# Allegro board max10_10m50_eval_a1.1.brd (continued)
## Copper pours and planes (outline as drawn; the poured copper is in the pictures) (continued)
1.8V_AVDD on BOTTOM (solid shape): 71.63,61.09 72.77,61.09 73.15,60.71 73.15,59.31 73.03,59.18 73.03,55.63 71.5,55.63 70.1,55.75 70.1,56.01 70.87,56.01 70.87,56.39 70.48,56.39 70.48,56.01 70.1,56.01 70.1,57.53 72.39,57.53 72.39,58.04 71.88,58.04 71.88,57.53 70.1,57.53 70.61,58.04 70.61,58.93 70.74,59.05 71.25,59.05 71.37,58.93 72.26,58.93 72.26,59.56 72.9,59.56 72.9,59.94 72.52,59.94 72.52,59.56 72.26,59.56 72.26,60.2 72.9,60.2 72.9,60.58 72.52,60.58 72.52,60.2 72.26,60.2 72.26,60.45 72.14,60.58 70.99,60.58 70.61,60.96 70.61,61.34 70.74,61.47 71.25,61.47
1.8V_DVDD on TOP (solid shape): 68.07,57.66 68.07,57.28 67.94,57.15 62.87,57.15 62.48,56.77 62.48,55.12 62.36,54.99 61.98,54.99 61.72,55.24 61.72,57.15 62.48,57.91 67.82,57.91
1.8V_DVDD on BOTTOM (solid shape): 63.37,57.4 64.9,57.4 64.9,54.61 62.36,54.61 61.98,54.99 61.98,56.26 64.01,56.26 64.01,56.77 63.5,56.77 63.5,56.26 61.98,56.26 61.98,57.4 62.23,57.66 63.12,57.66
1.8V_DVDD on ART04 (solid shape): 71.25,65.91 71.25,65.15 70.99,64.9 70.74,64.9 69.22,66.42 64.77,66.42 63.88,65.53 63.88,57.91 63.5,57.53 63.5,55.88 62.48,54.86 61.98,54.86 61.72,55.12 61.72,57.28 62.99,58.55 62.99,62.1 62.1,62.99 62.1,65.91 63.5,67.31 69.85,67.31
1.8V_MIPITX on BOTTOM (solid shape): 32.77,32.38 34.42,32.38 34.42,31.88 32.51,31.88 32,32.38 29.84,32.38 29.59,32.13 26.42,32.13 26.42,32.51 27.18,32.51 27.56,32.89 32.26,32.89
1.8V_OV10640 on BOTTOM (solid shape): 78.74,32.51 84.71,32.51 84.96,32.26 84.96,30.99 81.92,30.99 81.28,31.62 84.07,31.62 84.07,32.13 82.93,32.13 82.93,31.62 82.17,31.62 82.17,32.13 81.66,32.13 81.66,31.62 81.28,31.62 81.03,31.88 78.61,31.88 78.11,32.38 76.71,32.38 76.71,32.89 78.36,32.89
1.8V_PVDD on BOTTOM (solid shape): 69.6,57.53 69.6,55.75 66.8,55.75 66.8,54.48 65.79,54.48 65.79,56.01 69.22,56.01 69.22,56.39 68.45,56.39 68.45,56.01 68.2,56.01 68.2,56.39 67.82,56.39 67.82,56.01 65.79,56.01 65.79,57.4 66.8,57.4 66.8,56.77 67.94,56.77 68.33,57.15 68.33,57.53 68.58,57.78 69.34,57.78
2.5V on BOTTOM (solid shape): 40.26,49.15 39.75,48.64 38.73,48.64 38.48,48.89 38.48,50.16 38.73,50.42 41.15,50.42
2.5V on BOTTOM (solid shape): 27.23,55.78 27.38,55.63 27.94,55.63 28.32,55.24 28.32,54.61 25.4,54.61 25.02,54.99 25.02,55.5 26.29,55.5 26.29,56.01 25.78,56.01 25.78,55.5 25.02,55.5 25.02,56.39 25.27,56.64 27.23,56.64
2.5V on TOP: 25.91,56.64 27.23,56.64 27.23,55.78 27.38,55.63 28.32,55.63 28.7,56.01 30.1,56.01 30.23,55.88 30.23,54.48 29.97,54.23 25.4,54.23 25.02,54.61 25.02,56.01 25.15,56.13 25.65,56.13 25.78,56.26 25.78,56.52 ; 1 cut-out
2.5V on VCC03: 1.78,22.23 12.45,22.23 13.21,22.99 13.21,37.97 13.97,38.73 15.88,38.73 22.99,45.85 24.26,45.85 26.04,47.62 26.04,51.69 24.13,53.59 24.13,56.13 24.64,56.64 33.53,56.64 41.91,48.26 41.91,42.04 41.66,41.78 28.07,41.78 21.59,35.31 21.59,29.84 22.23,29.21 24.51,29.21 25.02,28.7 25.02,14.35 26.29,13.08 31.11,13.08 31.88,13.84 41.4,13.84 47.5,19.94 47.5,20.95 53.21,26.67 53.21,32.77 54.48,34.04 60.07,34.04 61.72,32.38 82.55,32.38 87.25,27.69 91.44,27.69 92.33,26.8 92.33,6.86 92.2,6.73 1.65,6.73 1.65,22.1
2.5V_CORE on BOTTOM (solid shape): 43.43,50.04 43.43,47.12 43.18,46.86 41.91,46.86 41.91,50.42 43.05,50.42
2.5V_VCCA on BOTTOM (solid shape): 53.47,40.89 53.47,40.39 52.96,40.39 52.83,40.51 52.83,40.89 52.58,41.15 51.31,41.15 51.18,41.27 51.18,41.4 51.31,41.53 52.83,41.53
2.5V_VCCA on BOTTOM (solid shape): 41.15,44.45 41.4,44.2 42.8,44.2 43.18,43.81 43.81,43.81 43.81,42.93 45.47,41.27 46.99,41.27 47.24,41.02 47.24,40.89 46.23,40.89 45.97,40.64 44.7,40.64 42.29,43.05 43.56,43.05 43.56,43.43 43.18,43.43 43.18,43.05 42.29,43.05 42.16,43.18 40.39,43.18 39.62,43.94 39.62,44.45 40.39,44.45 40.39,44.96 39.88,44.96 39.88,44.45 39.62,44.45 39.62,45.72 40.39,45.72 40.39,46.23 39.88,46.23 39.88,45.72 39.62,45.72 39.62,47.75 39.88,48.01 41.15,48.01
3.3V on TOP (solid shape): 15.24,57.53 15.24,56.26 14.1,56.26 13.84,56.52 14.99,56.52 14.99,56.9 14.61,56.9 14.61,56.52 13.84,56.52 13.84,57.53 14.1,57.78 14.99,57.78
3.3V on TOP (solid shape): 19.81,12.7 43.18,12.7 43.94,11.94 43.94,7.37 44.2,7.11 50.93,7.11 51.44,7.62 54.48,7.62 54.86,7.24 54.86,6.6 54.36,6.1 43.56,6.1 42.67,6.99 42.67,11.3 42.55,11.43 17.65,11.43 17.02,12.07 17.02,13.21 17.27,13.46 19.05,13.46
3.3V on BOTTOM (solid shape): 73.03,68.33 73.03,66.42 71.75,66.42 71.75,68.33 71.88,68.45 72.9,68.45
3.3V on BOTTOM (solid shape): 54.86,7.24 54.86,6.6 54.36,6.1 51.44,6.1 51.18,6.35 51.18,6.86 51.44,7.11 51.94,7.11 52.32,7.49 54.61,7.49
3.3V on BOTTOM (solid shape): 87,36.83 87,35.69 86.11,34.8 84.07,34.8 84.07,35.43 85.34,35.43 85.34,35.94 84.84,35.94 84.84,35.43 84.07,35.43 84.07,36.83 84.33,37.08 86.74,37.08
3.3V on BOTTOM (solid shape): 64.14,13.32 64.14,12.32 63.88,12.07 60.45,12.07 60.33,12.19 60.33,12.57 60.96,12.57 60.96,12.95 60.58,12.95 60.58,12.57 60.33,12.57 60.33,13.34 60.96,13.34 61.09,13.47 63.99,13.47
3.3V on BOTTOM (solid shape): 51.74,39.49 51.74,38.81 51.81,38.73 51.81,38.1 51.43,37.72 49.91,37.72 49.78,37.85 49.78,38.1 49.91,38.23 49.91,38.27 50.01,38.37 50.01,38.67 49.91,38.77 49.91,39.24 50.16,39.24 50.29,39.12 50.67,39.12 51.22,39.67 51.56,39.67
3.3V on BOTTOM (solid shape): 37.21,74.8 37.21,73.28 36.96,73.02 35.56,73.02 35.43,72.9 35.43,72.01 32.26,72.01 32,71.75 30.35,71.75 30.23,71.88 30.23,72.64 34.54,72.64 34.54,73.15 33.4,73.15 33.4,72.64 32.64,72.64 32.64,73.15 32.13,73.15 32.13,72.64 30.23,72.64 30.23,73.28 29.97,73.53 29.46,73.53 29.46,74.8 29.72,75.06 36.96,75.06
3.3V on ART04 (solid shape): 12.95,25.91 12.95,20.07 19.3,13.72 19.3,12.07 19.05,11.81 16.76,11.81 10.41,18.16 10.41,25.91 10.79,26.29 12.57,26.29
3.3V on ART04 (solid shape): 63.76,13.21 63.75,13.21 63.75,12.07 63.63,11.94 59.05,11.94 59,11.89 58.99,11.88 58.75,11.73 58.6,11.49 58.6,11.48 56.77,9.65 56.77,8.13 55.24,6.6 51.44,6.6 51.18,6.86 51.18,8.25 51.82,8.89 54.61,8.89 55.12,9.4 55.12,10.16 56.79,11.83 56.8,11.83 57.09,12 57.26,12.29 57.26,12.3 58.42,13.46 63.51,13.46
3.3V on BOTTOM: 26.92,34.54 26.92,35.05 27.05,35.18 27.56,35.18 27.69,35.31 27.69,37.34 27.43,37.59 26.16,37.59 24.77,36.2 24.77,25.65 23.11,24 20.83,24 19.05,25.78 17.78,25.78 17.27,26.29 10.79,26.29 10.16,25.65 10.16,24.13 10.79,23.49 14.61,23.49 15.49,22.61 23.88,22.61 26.04,24.77 26.04,34.42 26.16,34.54 ; 1 cut-out
3.3V on VCC03: 51.82,39.75 51.82,39.5 51.56,39.24 50.29,39.24 47.75,41.78 42.67,41.78 42.42,42.04 42.42,48.51 33.78,57.15 24.38,57.15 23.62,56.39 23.62,53.47 25.53,51.56 25.53,47.75 24.13,46.35 22.86,46.35 15.75,39.24 13.84,39.24 12.7,38.1 12.7,23.11 12.32,22.73 1.78,22.73 1.65,22.86 1.65,29.59 1.78,29.72 7.24,29.72 8.51,30.99 8.51,33.53 8,34.04 7.11,34.04 5.59,35.56 5.59,37.34 6.73,38.48 8,38.48 8.64,39.12 8.64,41.15 6.86,42.93 1.91,42.93 1.65,43.18 1.65,74.55 75.18,74.55 75.44,74.3 75.44,67.82 74.8,67.18 49.66,67.18 48.9,66.42 48.9,60.2 50.04,59.05 60.33,59.05 62.74,56.64 92.33,56.64 92.33,35.05 92.2,34.92 85.72,34.92 85.34,35.31 85.34,36.83 85.6,37.08 88.65,37.08 89.15,37.59 89.15,51.56 88.77,51.94 72.39,51.94 65.91,45.47 63.02,45.47 58.07,40.51 52.58,40.51
3.3V on ART04: 29.34,36.7 27.81,35.18 26.42,35.18 25.4,36.2 25.4,38.61 24,40 24,40.13 28.45,40.13 29.21,39.37 32,39.37 32.77,40.13 32.77,40.51 32.51,40.77 29.72,40.77 28.57,41.91 28.57,45.09 29.84,46.35 34.16,46.35 34.29,46.23 34.29,45.97 32.51,44.2 32.51,42.8 34.67,40.64 34.67,36.96 34.42,36.7
3.3V_DVDD on BOTTOM (solid shape): 73.03,65.02 73.79,64.26 73.79,62.48 73.15,62.48 72.39,63.25 71.5,63.25 71.5,63.37 73.15,63.37 73.15,63.88 72.64,63.88 72.64,63.37 71.5,63.37 71.37,63.5 72.26,63.5 72.26,63.88 71.88,63.88 71.88,63.5 71.37,63.5 71.25,63.63 69.72,63.63 69.72,63.88 70.48,63.88 70.48,64.01 73.28,64.01 73.28,64.52 72.77,64.52 72.77,64.01 72.01,64.01 72.01,64.52 71.5,64.52 71.5,64.01 70.48,64.01 70.48,64.26 70.1,64.26 70.1,63.88 69.72,63.88 69.72,64.64 71.25,64.64 71.75,65.15 71.75,65.66 73.03,65.66
3.3V_MIPITX on BOTTOM (solid shape): 29.84,34.29 34.42,34.29 34.42,32.89 32.89,32.89 32.38,33.4 27.3,33.4 27.05,33.66 26.42,33.66 26.42,34.04 27.05,34.04 27.56,34.54 29.59,34.54
3.3V_OV5640 on TOP (solid shape): 57.28,13.34 57.28,11.43 56.77,10.92 55.12,10.92 55.12,13.34 55.5,13.72 56.9,13.72
3.3V_OV5640 on BOTTOM (solid shape): 59.18,13.34 59.82,13.34 59.82,12.83 59.18,12.83 58.93,12.57 57.28,12.57 56.77,12.07 55.63,12.07 55.37,12.32 55.37,13.34 55.63,13.59 58.93,13.59
3.3V_OV10640 on BOTTOM (solid shape): 81.66,33.91 84.96,33.91 84.96,32.89 79.38,32.89 78.87,33.4 76.71,33.4 76.71,34.16 76.96,34.42 81.15,34.42
3.3V_SI5338 on TOP (solid shape): 23.11,57.15 23.11,53.59 21.34,51.82 19.05,51.82 18.67,52.2 18.67,53.47 19.05,53.47 19.05,52.96 19.3,52.7 20.32,52.7 20.45,52.83 21.21,52.83 21.21,53.21 20.83,53.21 20.83,52.83 20.45,52.83 20.57,52.96 20.57,53.59 21.08,53.59 21.21,53.72 22.1,53.72 22.1,54.1 21.72,54.1 21.72,53.72 21.21,53.72 21.34,53.85 21.34,54.36 21.97,54.36 22.23,54.61 22.23,56.52 21.97,56.77 18.03,56.77 17.91,56.64 17.91,56.39 17.78,56.26 17.02,56.26 16.89,56.13 15.75,56.13 15.75,56.52 17.53,56.52 17.53,56.9 17.14,56.9 17.14,56.52 16.38,56.52 16.38,56.9 16,56.9 16,56.52 15.75,56.52 15.75,57.02 22.1,57.02 22.1,57.4 21.72,57.4 21.72,57.02 21.46,57.02 21.46,57.4 21.08,57.4 21.08,57.02 15.75,57.02 16,57.28 17.4,57.28 17.91,57.78 22.48,57.78
5V on TOP (solid shape): 92.08,60.96 92.08,59.31 91.82,59.05 90.04,59.05 89.53,58.55 89.53,56.9 90.04,56.39 92.2,56.39 92.96,55.63 92.96,51.82 92.71,51.56 91.31,51.56 91.31,52.45 92.46,52.45 92.46,52.96 91.95,52.96 91.95,52.45 91.31,52.45 91.31,54.86 90.93,55.24 89.03,55.24 87.63,56.64 87.63,59.69 89.15,61.21 91.82,61.21
5V on BOTTOM (solid shape): 24.13,30.48 24.38,30.23 24.38,28.19 24.13,27.94 22.99,27.94 22.73,28.19 22.73,30.23 23.11,30.61 23.11,31.88 24.13,31.88
5V on BOTTOM (solid shape): 29.46,61.34 29.46,58.55 28.45,58.55 28.45,58.67 27.94,59.18 26.04,59.18 25.78,59.44 28.7,59.44 28.7,59.94 28.19,59.94 28.19,59.44 25.78,59.44 25.4,59.82 25.4,61.21 25.78,61.59 29.21,61.59
5V on BOTTOM (solid shape): 51.31,62.23 51.82,62.23 52.58,61.47 52.58,60.71 52.2,60.32 50.16,60.32 48.77,61.72 48.77,62.48 50.16,62.48 50.16,62.99 49.66,62.99 49.66,62.48 48.77,62.48 48.77,63.63 49.91,63.63
5V on BOTTOM (solid shape): 22.86,74.3 22.86,72.14 22.61,71.88 20.32,71.88 19.81,72.39 19.81,72.64 22.48,72.64 22.48,73.15 21.97,73.15 21.97,72.64 21.21,72.64 21.21,73.15 20.7,73.15 20.7,72.64 19.81,72.64 19.81,74.3 20.07,74.55 22.61,74.55
5V on TOP: 18.03,39.88 18.03,35.31 17.78,35.05 16.51,35.05 16.26,35.31 16.26,37.85 16.89,38.48 16.89,39.88
5V on BOTTOM: 11.43,38.99 16.64,38.99 18.41,37.21 18.41,35.56 18.16,35.31 16.13,35.31 15.75,35.69 15.75,36.7 14.99,37.46 13.46,37.46 13.08,37.85 11.43,37.85
5V on VCC03: 60.45,59.56 62.87,57.15 92.2,57.15 92.33,57.28 92.33,74.55 76.2,74.55 75.95,74.3 75.95,67.44 75.18,66.67 50.04,66.67 49.4,66.04 49.4,60.45 50.29,59.56
5V on ART04: 22.23,27.94 16.76,33.4 14.86,33.4 10.29,37.97 10.29,41.78 4.45,47.62 4.45,66.67 9.14,71.37 15.62,71.37 18.8,74.55 22.1,74.55 22.35,74.3 22.35,73.15 23.37,72.14 25.91,72.14 27.94,74.17 32.13,74.17 33.78,72.52 41.53,72.52 42.93,71.12 48.26,71.12 52.7,66.67 52.7,60.71 52.32,60.32 49.91,60.32 45.47,64.77 33.02,64.77 28.45,60.2 24.89,60.2 20.32,64.77 8.89,64.77 7.75,65.91 7.37,65.91 6.99,65.53 6.99,61.59 7.62,60.96 7.62,47.37 16.38,38.61 19.68,38.61 21.84,36.45 21.84,35.31 24.77,32.38 24.77,28.19 24.51,27.94 ; 1 cut-out
5V_DCIN on TOP (solid shape): outline of 86 points within 5.71,12.07 14.1,19.05
5V_MONITOR on BOTTOM (solid shape): 25.02,21.97 25.02,19.05 21.59,19.05 21.34,18.8 20.19,18.8 19.81,18.41 18.92,18.41 18.92,18.92 19.56,18.92 19.68,19.05 21.08,19.05 21.08,19.43 20.7,19.43 20.7,19.05 20.45,19.05 20.45,19.43 20.07,19.43 20.07,19.05 19.68,19.05 19.68,19.43 20.07,19.81 20.07,22.23 24.77,22.23
5V_MONITOR on TOP: 25.78,19.81 25.53,20.07 19.94,20.07 19.43,20.57 15.88,20.57 15.62,20.83 15.62,22.73 18.8,22.73 19.05,22.48 21.84,22.48 22.48,23.11 22.48,26.42 24.13,28.07 24.13,34.29 23.62,34.8 18.8,34.8 18.41,35.18 18.41,37.72 18.8,38.1 18.8,39.88 20.7,39.88 23.5,37.08 25.91,37.08 26.29,36.7 26.29,35.18 27.69,33.78 27.69,26.42 26.04,24.77 26.04,20.19 26.1,20.13
5V_R1.2CORE on TOP (solid shape): 15.49,28.19 15.49,25.91 15.24,25.65 14.73,25.65 14.48,25.91 14.48,28.07 14.73,28.32 15.37,28.32
5V_R1.2CORE on TOP (solid shape): 21.84,28.19 21.59,27.94 20.32,27.94 20.19,28.07 18.92,28.07 18.8,28.19 18.8,28.96 18.92,29.08 19.56,29.08 19.94,29.46 19.94,30.61 20.19,30.86 21.84,30.86
5V_R1.2CORE on BOTTOM (solid shape): 22.35,28.19 22.1,27.94 19.94,27.94 19.68,28.19 19.68,30.48 21.59,30.48 21.59,30.99 21.08,30.99 21.08,30.48 19.68,30.48 19.68,30.86 20.7,31.88 22.35,31.88
5V_R1.2VCCIO on TOP (solid shape): 90.93,54.61 90.93,53.47 90.3,52.83 90.3,51.56 89.15,51.56 88.27,52.45 89.66,52.45 89.66,52.96 89.15,52.96 89.15,52.45 88.27,52.45 88.27,54.23 88.9,54.23 88.9,54.61 88.52,54.61 88.52,54.23 88.27,54.23 88.27,54.86 90.68,54.86
5V_R1.2VCCIO on BOTTOM (solid shape): 90.93,54.48 90.93,52.2 89.53,52.2 89.03,52.7 88.39,52.7 88.27,52.83 90.04,52.83 90.04,53.34 89.53,53.34 89.53,52.83 88.27,52.83 88.27,54.36 88.52,54.61 90.81,54.61
5V_R1.8 on BOTTOM (solid shape): 52.58,64.64 53.09,64.64 53.09,63.25 53.47,62.86 53.59,62.86 53.72,62.74 53.72,61.98 53.59,61.85 52.83,61.85 52.07,62.61 51.69,62.61 49.91,64.39 52.07,64.39 52.07,64.9 51.56,64.9 51.56,64.39 49.91,64.39 49.78,64.52 48.77,64.52 48.77,65.53 51.69,65.53
5V_R2.5 on TOP (solid shape): 31.75,60.71 33.4,60.71 33.53,60.58 33.53,59.18 33.27,58.93 32.26,58.93 31.5,58.17 30.48,58.17 30.48,59.05 30.35,59.18 30.35,59.56 31.5,59.56 31.5,60.07 30.99,60.07 30.99,59.56 30.35,59.56 30.35,60.96 31.5,60.96
5V_R2.5 on BOTTOM (solid shape): 33.91,60.45 33.91,57.91 33.53,57.91 33.53,58.42 33.27,58.67 32.38,58.67 32.26,58.55 30.35,58.55 30.35,59.44 31.5,59.44 31.5,59.94 30.99,59.94 30.99,59.44 30.35,59.44 30.35,60.45 30.61,60.71 33.66,60.71
5V_R3.3 on BOTTOM (solid shape): 31.62,69.34 31.62,67.69 31.37,67.44 30.48,67.44 30.23,67.69 30.23,69.85 30.35,69.98 30.99,69.98
5V_R3.3 on BOTTOM (solid shape): 26.16,70.74 26.8,70.74 26.92,70.61 26.92,69.85 26.8,69.72 25.65,69.72 24.51,68.58 21.46,68.58 21.08,68.96 21.08,69.85 22.48,69.85 22.48,70.36 21.97,70.36 21.97,69.85 21.08,69.85 21.08,71.12 25.78,71.12
GND on TOP (solid shape): 69.22,59.05 64.14,59.05 64.14,64.14 69.22,64.14
GND on TOP (solid shape): 21.84,34.04 21.84,31.62 19.94,31.62 18.54,33.02 17.91,33.02 17.65,32.77 17.65,26.92 16,26.92 16,29.21 16.89,29.21 16.89,31.5 16.64,31.75 16.64,34.04 16.89,34.29 21.59,34.29
GND on TOP (solid shape): 15.49,29.59 15.49,28.83 15.37,28.7 14.48,28.7 14.1,28.32 14.1,26.92 13.84,26.67 10.54,26.67 10.16,27.05 10.16,29.46 13.72,29.46 13.97,29.72 15.37,29.72
GND on TOP (solid shape): 57.15,69.22 57.15,68.2 54.61,65.66 50.8,65.66 50.55,65.91 54.23,65.91 54.23,66.29 53.85,66.29 53.85,65.91 53.59,65.91 53.59,66.29 53.21,66.29 53.21,65.91 50.55,65.91 50.55,70.99 55.37,70.99
GND on BOTTOM (solid shape): 20.83,54.1 18.54,54.1 18.54,56.39 20.83,56.39
GND on BOTTOM (solid shape): 21.84,42.29 16.26,42.29 16.26,47.88 21.84,47.88
GND on BOTTOM (solid shape): 17.78,31.37 17.78,26.92 17.53,26.67 16.08,26.67 15.88,26.87 15.88,31.37 16.13,31.62 17.53,31.62
GND on BOTTOM (solid shape): 35.43,40.13 36.7,40.13 36.7,39.12 35.43,39.12 35.18,38.86 34.92,38.86 34.8,38.99 34.8,40.13 34.92,40.26 35.31,40.26
GND on BOTTOM (solid shape): 29.97,31.12 29.97,30.1 29.72,29.84 28.19,29.84 28.07,29.97 28.07,31.12 29.21,31.12 29.46,31.37 29.72,31.37
GND on BOTTOM (solid shape): 64.14,66.55 60.33,66.55 59.31,65.53 58.55,65.53 58.29,65.79 58.29,66.55 59.44,67.69 64.14,67.69
GND on BOTTOM (solid shape): 19.3,20.7 19.68,20.32 19.68,20.07 19.3,19.69 18.92,19.69 18.54,19.3 17.14,19.3 16.76,18.92 16.76,18.41 16.64,18.29 16.13,18.29 15.88,18.54 15.88,21.97 16.13,22.23 19.3,22.23
GND on BOTTOM (solid shape): 24.89,61.34 24.89,59.56 25.91,58.55 27.81,58.55 28.07,58.29 28.07,57.91 27.81,57.66 26.04,57.66 25.78,57.4 22.23,57.4 21.21,58.42 21.21,61.21 21.59,61.59 24.64,61.59
GND on BOTTOM (solid shape): 44.83,45.97 44.83,43.56 44.7,43.43 44.32,43.43 43.94,44.58 43.43,44.58 43.18,44.83 41.91,44.83 41.91,45.85 42.85,45.85 43.23,46.23 44.58,46.23
GND on BOTTOM (solid shape): 83.06,25.65 82.8,25.4 82.17,25.4 81.66,24.89 81.41,24.89 81.28,25.02 81.28,28.83 82.17,28.83 82.17,29.34 81.66,29.34 81.66,28.83 81.28,28.83 81.28,29.84 81.41,29.97 83.06,29.97
GND on BOTTOM (solid shape): 29.08,74.8 29.08,73.41 28.83,73.15 28.83,70.87 29.72,70.87 29.72,68.71 28.07,68.71 28.07,74.42 27.94,74.55 26.8,74.55 25.78,73.53 25.78,72.14 25.53,71.88 23.5,71.88 23.5,74.8 23.75,75.06 28.83,75.06
GND on BOTTOM (solid shape): 15.49,29.46 15.49,26.92 15.24,26.67 10.54,26.67 10.16,27.05 10.16,28.96 15.24,28.96 15.24,29.34 14.86,29.34 14.86,28.96 10.16,28.96 10.16,29.46 13.97,29.46 14.1,29.59 15.37,29.59
GND on BOTTOM (solid shape): 32.26,70.99 35.43,70.99 35.43,69.6 35.18,69.34 32.26,69.34 31.75,69.85 34.54,69.85 34.54,70.36 33.4,70.36 33.4,69.85 32.64,69.85 32.64,70.36 32.13,70.36 32.13,69.85 31.75,69.85 31.24,70.36 30.35,70.36 30.23,70.48 30.23,71.25 30.35,71.37 31.88,71.37
GND on BOTTOM (solid shape): 70.61,52.83 69.22,51.43 67.56,51.43 67.31,51.69 67.31,54.61 70.23,54.61 70.23,54.99 69.47,54.99 69.47,54.61 69.22,54.61 69.22,54.99 68.45,54.99 68.45,54.61 68.2,54.61 68.2,54.99 67.82,54.99 67.82,54.61 67.31,54.61 67.31,54.99 67.56,55.24 70.61,55.24
GND on BOTTOM (solid shape): 12.83,44.45 13.59,44.45 13.59,44.07 12.75,44.07 12.75,44.07 11.26,44.07 11.26,43.89 11.18,43.81 11.18,42.93 10.29,42.93 10.16,42.8 10.16,42.62 10.11,42.62 10.11,41.02 11.6,41.02 12.83,41.02 13.21,41.02 13.21,41.4 12.83,41.4 12.83,41.02 11.6,41.02 11.6,41.2 11.68,41.27 11.68,42.16 12.32,42.16 12.32,41.66 13.59,41.66 13.59,40.64 13.46,40.51 10.29,40.51 9.78,41.02 9.78,43.31 11.18,44.7 12.57,44.7
GND on BOTTOM (solid shape): 54.1,67.06 53.98,66.93 53.21,66.93 53.09,67.06 52.83,67.06 52.32,66.55 49.91,66.55 49.66,66.8 49.66,67.18 52.07,67.18 52.07,67.69 51.56,67.69 51.56,67.18 50.8,67.18 50.8,67.69 50.29,67.69 50.29,67.18 49.66,67.18 49.66,69.72 53.34,69.72 53.34,70.23 52.83,70.23 52.83,69.72 49.66,69.72 49.66,70.61 50.16,71.12 54.1,71.12
GND on BOTTOM (solid shape): 44.83,61.09 44.83,59.56 44.58,59.31 44.2,59.31 43.94,59.56 43.94,60.83 43.31,61.47 40.39,61.47 40.13,61.21 40.13,54.36 40.39,54.1 42.67,54.1 43.05,54.48 43.05,54.86 43.56,54.86 43.56,53.85 43.43,53.72 34.04,53.72 33.53,54.23 33.53,54.99 34.67,56.13 34.67,58.42 34.92,58.42 34.92,55.88 35.81,54.99 35.81,54.48 36.2,54.1 38.35,54.1 38.61,54.36 38.61,59.31 38.35,59.56 36.07,59.56 34.92,58.42 34.67,58.42 34.67,60.58 36.07,61.98 43.94,61.98
GND on BOTTOM (solid shape): 20.7,61.21 20.7,58.67 20.45,58.42 19.81,58.42 19.81,58.8 20.45,58.8 20.45,59.18 20.07,59.18 20.07,58.8 19.81,58.8 19.81,59.56 19.94,59.69 19.94,60.32 19.81,60.45 19.81,60.71 19.68,60.83 18.67,60.83 18.67,61.59 18.41,61.85 17.02,61.85 16.89,61.72 16.89,60.58 17.14,60.32 18.03,60.32 18.03,59.69 17.4,59.69 17.4,58.42 17.91,57.91 17.91,57.66 17.65,57.4 16.76,57.4 16.38,57.78 16.38,58.17 17.14,58.17 17.14,58.55 16.76,58.55 16.76,58.17 16.38,58.17 16.38,58.8 17.14,58.8 17.14,59.18 16.76,59.18 16.76,58.8 16.38,58.8 16.38,61.85 16.64,62.1 19.81,62.1
GND on BOTTOM (solid shape): 37.97,36.2 37.97,26.16 37.85,26.03 37.72,26.03 37.59,26.16 37.59,26.29 37.47,26.42 37.08,26.42 36.7,26.8 37.72,26.8 37.72,27.43 37.34,27.43 37.34,26.8 36.7,26.8 36.7,27.69 37.72,27.69 37.72,28.07 37.34,28.07 37.34,27.69 36.7,27.69 36.7,28.83 37.72,28.83 37.72,29.21 37.34,29.21 37.34,28.83 36.7,28.83 36.7,29.46 37.72,29.46 37.72,30.1 37.34,30.1 37.34,29.46 36.7,29.46 36.7,30.35 37.72,30.35 37.72,30.73 37.34,30.73 37.34,30.35 36.7,30.35 36.7,31.5 37.72,31.5 37.72,31.88 37.34,31.88 37.34,31.5 36.7,31.5 36.7,32.13 37.72,32.13 37.72,32.77 37.34,32.77 37.34,32.13 36.7,32.13 36.7,33.02 37.72,33.02 37.72,33.4 37.34,33.4 37.34,33.02 36.7,33.02 36.7,34.67 37.72,34.67 37.72,35.31 37.34,35.31 37.34,34.67 36.7,34.67 36.7,35.56 37.72,35.56 37.72,35.94 37.34,35.94 37.34,35.56 36.7,35.56 36.7,36.2 36.83,36.32 37.85,36.32
GND on BOTTOM (solid shape): outline of 117 points within 27.69,24.64 35.94,42.55
GND on BOTTOM (solid shape): outline of 109 points within 63.88,54.23 81.28,65.53
GND on BOTTOM (solid shape): outline of 1763 points within 1.14,6.1 52.45,20.95
GND on TOP: 9.78,35.05 7.24,35.05 6.99,34.8 6.99,34.42 7.49,33.91 8.13,33.91 8.51,33.53 8.51,30.99 7.24,29.72 1.27,29.72 1.14,29.59 1.14,26.92 1.27,26.8 7.11,26.8 8.26,27.94 8.26,29.21 9.02,29.97 9.02,30.73 9.78,31.5 9.78,33.91 10.03,34.16 10.03,34.8
GND on TOP: outline of 133 points within 28.83,6.1 92.96,75.06 ; 8 cut-outs
GND on TOP: 39.12,54.99 39.12,59.56 38.86,59.82 37.34,59.82 37.08,60.07 37.08,67.06 36.7,67.44 32.51,67.44 31.24,68.71 31.24,71.25 31.5,71.5 31.62,71.5 32.51,70.61 34.54,70.61 35.94,69.22 40.01,69.22 41.27,67.95 41.27,63.5 40.01,62.23 40.01,54.99
GND on TOP: 30.23,68.83 29.97,68.58 28.96,68.58 27.43,70.1 27.43,72.26 28.45,73.28 28.83,73.28 30.23,71.88
GND on TOP: 14.61,59.05 13.97,59.69 13.97,62.23 14.99,63.25 14.99,66.55 15.37,66.93 22.86,66.93 23.11,66.67 23.11,63.63 24.13,63.63 24.13,62.86 26.04,60.96 29.34,60.96 29.34,59.05 29.08,58.8 28.7,58.8 28.45,58.55 28.45,57.91 28.19,57.66 25.91,57.66 25.65,57.91 25.02,57.91 24.51,57.4 24.26,57.4 22.61,59.05 ; 3 cut-outs
GND on TOP: 31.37,26.29 29.21,26.29 28.83,26.67 28.83,29.46 29.21,29.84 29.84,29.84 30.1,30.1 30.1,32.51 29.84,32.77 28.45,32.77 28.07,32.38 28.07,26.16 26.67,24.77 26.67,22.61 27.05,22.23 27.94,22.23 33.02,17.14 35.81,17.14 37.34,18.67 37.34,20.83 36.32,21.84 32.64,21.84 31.37,23.11
GND on TOP: 1.14,6.1 1.02,6.22 1.02,24.64 1.14,24.77 8.13,24.77 9.78,23.11 9.78,20.07 9.27,19.56 6.1,19.56 5.21,18.67 5.21,12.45 6.1,11.56 9.91,11.56 10.04,11.43 9.53,9.41 10.16,7.43 10.16,6.22 10.03,6.1
GND on TOP: outline of 82 points within 1.02,38.86 25.78,56.39 ; 23 cut-outs
GND on BOTTOM: 57.02,6.1 56.77,6.35 56.77,11.56 56.9,11.68 63.88,11.68 63.88,9.14 66.55,9.14 66.55,10.79 73.79,10.79 74.3,11.3 74.3,12.7 74.68,13.08 81.28,13.08 84.96,16.76 84.96,18.54 85.47,19.05 87,19.05 88.9,20.95 88.9,24.13 89.66,24.89 89.66,27.69 89.92,27.94 90.81,27.94 91.06,28.19 91.06,34.92 92.33,36.2 92.33,47.24 92.71,47.62 92.71,55.75 91.69,56.77 90.3,56.77 89.92,57.15 89.92,65.02 87.88,67.06 83.31,67.06 83.19,67.18 83.19,74.93 83.31,75.06 92.71,75.06 92.84,74.93 92.84,56.77 92.96,56.64 92.96,12.32 92.71,12.07 92.4,12.07 86.83,12.23 87,6.66 87,6.48 86.61,6.1 ; 2 cut-outs
GND on BOTTOM: 1.27,42.8 1.14,42.93 1.14,44.83 1.27,44.96 6.1,44.96 6.48,45.34 6.48,46.86 10.16,46.86 10.54,46.48 10.54,46.1 8.38,43.94 8.38,43.43 7.49,43.43 6.86,42.8 ; 4 cut-outs
GND on BOTTOM: outline of 87 points within 64.26,23.37 90.93,51.18 ; 16 cut-outs
GND on BOTTOM: 83.31,47.24 83.06,47.5 82.3,47.5 82.3,48.26 82.17,48.39 81.41,48.39 81.41,49.53 80.9,50.04 79.88,50.04 77.47,47.62 77.47,45.59 77.22,45.34 76.83,45.34 76.58,45.09 76.58,44.7 76.33,44.45 75.06,44.45 74.8,44.2 66.42,44.2 65.15,45.47 65.15,48.26 65.91,49.02 69.22,49.02 69.22,47.5 68.83,47.12 68.83,46.23 66.17,46.23 65.91,45.97 65.91,45.34 66.29,44.96 70.99,44.96 72.26,46.23 72.26,50.67 73.53,51.94 77.34,51.94 83.69,58.29 86.61,58.29 87,57.91 87,57.02 86.36,56.39 86.36,53.59 85.6,52.83 84.33,52.83 83.44,51.94 83.44,48.01 83.69,47.75 83.69,46.61 83.31,46.61 ; 5 cut-outs
GND on GND02: 1.14,6.1 1.02,6.22 1.02,22.61 1.27,22.61 1.27,24.13 1.02,24.13 1.02,25.15 1.27,25.15 1.27,26.67 1.02,26.67 1.02,29.59 1.14,29.72 7.24,29.72 8.51,30.99 8.51,33.53 8,34.04 6.86,34.04 5.59,35.31 5.59,37.34 6.73,38.48 8,38.48 8.64,39.12 8.64,41.15 6.86,42.93 1.14,42.93 1.02,43.05 1.02,75.06 1.14,75.18 92.84,75.18 92.96,75.06 92.96,6.22 92.84,6.1 ; 1 cut-out
GND on GND05: 1.14,6.1 1.02,6.22 1.02,22.61 1.27,22.61 1.27,23.24 1.78,23.24 1.78,23.88 1.02,23.88 1.02,25.15 1.27,25.15 1.27,26.67 1.02,26.67 1.02,29.59 1.14,29.72 7.24,29.72 8.51,30.99 8.51,33.53 8,34.04 6.86,34.04 5.59,35.31 5.59,37.34 6.73,38.48 8,38.48 8.64,39.12 8.64,41.15 6.86,42.93 1.14,42.93 1.02,43.05 1.02,75.06 1.14,75.18 92.84,75.18 92.96,75.06 92.96,6.22 92.84,6.1 ; 1 cut-out
GND_EARTH on TOP, GND02: 6.6,42.04 7.75,40.89 7.75,39.5 7.37,39.12 5.84,39.12 4.57,37.85 4.57,34.42 5.59,33.4 7.24,33.4 7.75,32.89 7.75,31.88 6.6,30.73 1.14,30.73 1.02,30.86 1.02,41.91 1.14,42.04
GND_EARTH on BOTTOM: 1.14,42.16 1.27,42.29 6.35,42.29 7.75,40.89 7.75,39.5 7.37,39.12 5.84,39.12 4.57,37.85 4.57,34.42 5.59,33.4 7.37,33.4 7.37,31.5 6.6,30.73 1.27,30.73 1.14,30.86 ; 4 cut-outs
GND_EARTH on VCC03: 1.78,42.04 6.6,42.04 7.75,40.89 7.75,39.5 7.37,39.12 5.84,39.12 4.57,37.85 4.57,34.42 5.59,33.4 7.24,33.4 7.75,32.89 7.75,31.88 6.6,30.73 1.78,30.73 1.65,30.86 1.65,41.91
GND_EARTH on ART04, GND05: 6.6,42.04 7.75,40.89 7.75,39.5 7.37,39.12 5.84,39.12 4.57,37.85 4.57,34.42 5.59,33.4 7.24,33.4 7.75,32.89 7.75,31.88 6.6,30.73 1.14,30.73 1.02,30.86 1.02,41.91 1.14,42.04
VBUS_5V on TOP: 15.49,38.35 15.88,37.97 15.88,35.43 15.24,34.8 10.92,34.8 8.76,36.96 7.37,36.96 6.99,37.34 6.99,38.48 7.37,38.86 9.02,38.86 9.53,38.35
VBUS_5V on BOTTOM: 11.43,37.08 14.99,37.08 15.37,36.7 15.37,35.18 14.99,34.8 11.68,34.8 11.43,35.05
N16939055 on TOP (solid shape): 14.86,18.03 13.84,17.02 11.68,17.02 11.43,17.27 11.43,23.11 11.68,23.37 14.86,23.37

Small or netless copper shapes (teardrops, artwork), in the pictures only: 19 on TOP

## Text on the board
Ref Des/Silkscreen Bottom: 100-0321404-A1.1 REV.A1.1 | 2015 ALTERA CORP. | C | A | S/N
Ref Des/Silkscreen Top: LED4 | LED3 | LED2 | LED1 | LED0 | POWER SWITCH | USB | DC INPUT 5V | 5V | J11 | 1-2 | 2-3 | USB_5V | DC_5V | POWER | RESETN | 2.5V | NCONFIG | AB | G | R | SW2 | 1 | 2 | 3 | 4 | 7 | USER_DIPSW4 | USER_DIPSW5 | CONFIG_SEL | BYPASSN | FUNCTION | 10M50 EVALUATION KIT | 15 | USER_PB3 | 22 | USER_PB2 | SW1 | USER_DIPSW0 | USER_DIPSW1 | USER_DIPSW2 | USER_DIPSW3 | HDMI | USER_PB0 | USER_PB1 | 1.2V | CONF_DONE
DEVICE_TYPE_TOP: FIGURE | SIZE | 8.0 | 10.0 | 12.0 | 13.0 | 28.0 | 30.0 | 39.37 | 40.0 | 45.0 | 125.0 | 118.11 | 75.0x36.0 | 83.0x35.0 | 106.0x35.0 | 138.0x31.0 | DRILL CHART: TOP to BOTTOM | ALL UNITS ARE IN MILS | TOLERANCE | +0.0/-0.0 | +3.0/-3.0 | PLATED | NON-PLATED | QTY | 615 | 503 | 184 | 68 | 5 | 6 | 40 | 24 | 14 | 3 | 4 | 2 | 1
